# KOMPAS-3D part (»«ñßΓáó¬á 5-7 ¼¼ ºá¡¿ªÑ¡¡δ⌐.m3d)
File: created 10.02.2016 13:21:24, last saved 23.07.2016 22:13:14.
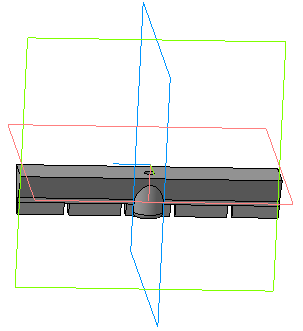
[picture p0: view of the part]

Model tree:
1. Эскиз:1
2. Операция выдавливания:1
     Расстояние 1 = 25.3; Расстояние 2 = 25.3
3. Эскиз:2
4. Вырезать элемент выдавливания:1
     Расстояние 1 = 2.5
5. Эскиз:3
6. Вырезать элемент выдавливания:2
     Расстояние 1 = 60
7. Эскиз:4
8. Операция выдавливания:2
     Расстояние 1 = 10; Расстояние 2 = 8.5
9. Эскиз:5
10. Вырезать элемент выдавливания:3
     Расстояние 1 = 50
11. Эскиз:6
12. Вырезать элемент выдавливания:4
     Расстояние 1 = 3; Угол 1 = 32
13. Скругление:1
     Радиус = 1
